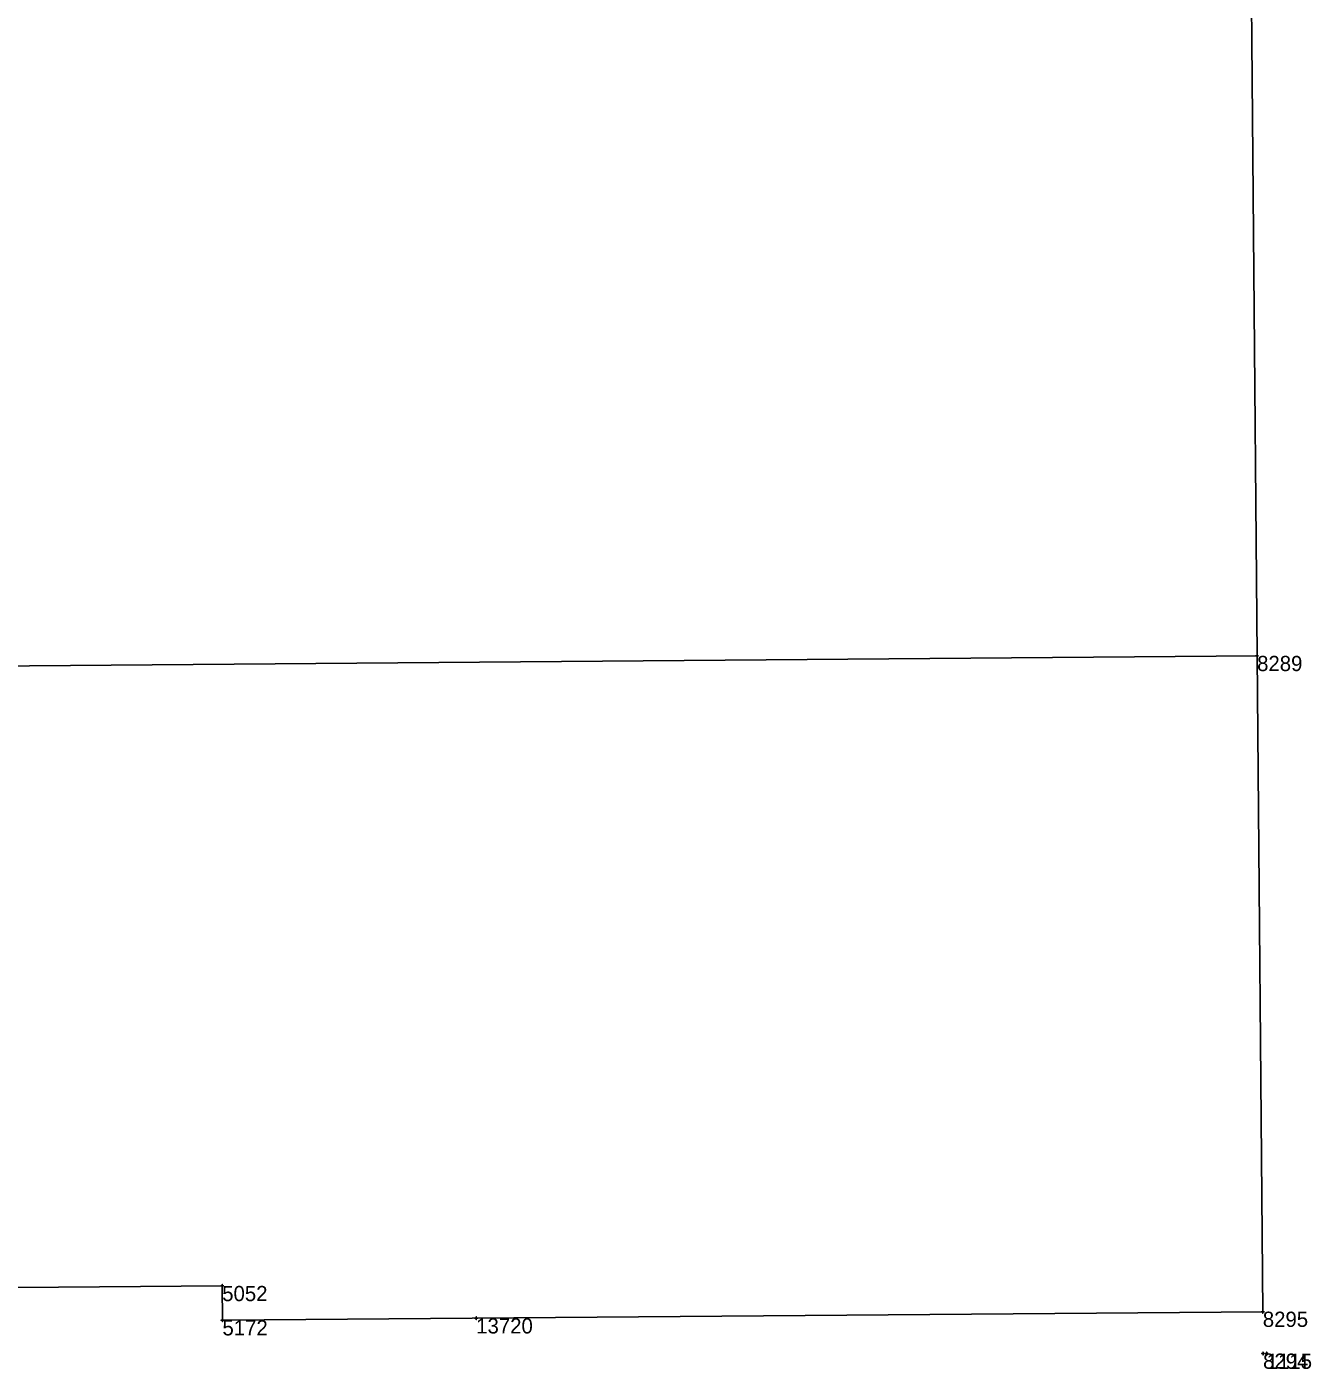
# Model space of a CAD drawing. Extents: x 2145146 to 2158053, y 137507 to 150829.
# Drawn here: x 2151313 to 2152326, y 137719 to 138777 of the extents above; entities that cross this region are included whole.
import ezdxf

# ---------------------------------------------------------------- set-up
doc = ezdxf.new("R2010")
doc.units = 0
for name, color, linetype in [('ALIGN_Cogo Points', 7, 'Continuous'), ('ALIGN_ROW Line', 7, 'Continuous'), ('PLSS_Property Line', 7, 'Continuous')]:
    doc.layers.add(name, color=color, linetype=linetype)

msp = doc.modelspace()

# ---------------------------------------------------------------- linework, layer by layer
at = {"layer": 'ALIGN_Cogo Points'}
for points in [[(2152283.1, 138281.1), (2152283.1, 138282.3), (2152283.1, 138281.1), (2152281.9, 138281.1), (2152283.1, 138281.1), (2152283.1, 138279.9), (2152283.1, 138281.1), (2152284.3, 138281.1)], [(2151467.4, 137784.4), (2151467.4, 137785.6), (2151467.4, 137784.4), (2151466.2, 137784.4), (2151467.4, 137784.4), (2151467.4, 137783.2), (2151467.4, 137784.4), (2151468.6, 137784.4)], [(2151467.6, 137757.4), (2151467.6, 137758.6), (2151467.6, 137757.4), (2151466.4, 137757.4), (2151467.6, 137757.4), (2151467.6, 137756.2), (2151467.6, 137757.4), (2151468.8, 137757.4)], [(2151667.6, 137758.9), (2151667.6, 137760.1), (2151667.6, 137758.9), (2151666.4, 137758.9), (2151667.6, 137758.9), (2151667.6, 137757.7), (2151667.6, 137758.9), (2151668.8, 137758.9)], [(2152287.6, 137764.1), (2152287.6, 137765.3), (2152287.6, 137764.1), (2152286.4, 137764.1), (2152287.6, 137764.1), (2152287.6, 137762.9), (2152287.6, 137764.1), (2152288.8, 137764.1)], [(2152287.8, 137731.1), (2152287.8, 137732.3), (2152287.8, 137731.1), (2152286.6, 137731.1), (2152287.8, 137731.1), (2152287.8, 137729.9), (2152287.8, 137731.1), (2152289, 137731.1)], [(2152290.7, 137731), (2152290.7, 137732.2), (2152290.7, 137731), (2152289.5, 137731), (2152290.7, 137731), (2152290.7, 137729.8), (2152290.7, 137731), (2152291.9, 137731)]]:
    msp.add_lwpolyline(points, dxfattribs=at)
at = {"layer": 'ALIGN_ROW Line'}
msp.add_lwpolyline([(2151467.6, 137757.4), (2151467.4, 137784.4), (2151080.4, 137781.2), (2151054.8, 137833.2), (2151025, 138270.8), (2151014.8, 138420.9), (2151013.1, 138620.9), (2151002.2, 138720.8), (2150992.1, 138720.5), (2150984.4, 139606.7), (2150993.3, 139722.5), (2151034.1, 140247.7), (2151053, 140291.9), (2151058.3, 140359.7), (2151125.2, 141214)], dxfattribs=at)
at = {"layer": 'PLSS_Property Line'}
for points in [[(2152283.1, 138281.1), (2152274.4, 139281.1), (2150987.3, 139270.5)], [(2152283.1, 138281.1), (2151025, 138270.8)], [(2151467.6, 137757.4), (2152287.6, 137764.1), (2152283.1, 138281.1)]]:
    msp.add_lwpolyline(points, dxfattribs=at)

# ---------------------------------------------------------------- texts
at = {"layer": 'ALIGN_Cogo Points'}
for s, p in [('8289', (2152283.1, 138269.1)), ('5052', (2151467.4, 137772.4)), ('5172', (2151467.6, 137745.4)), ('13720', (2151667.6, 137746.9)), ('8295', (2152287.6, 137752.1)), ('8294', (2152287.8, 137719.1)), ('1115', (2152290.7, 137719))]:
    msp.add_text(s, height=12, dxfattribs=at).set_placement(p)

doc.saveas('drawing.dxf')
